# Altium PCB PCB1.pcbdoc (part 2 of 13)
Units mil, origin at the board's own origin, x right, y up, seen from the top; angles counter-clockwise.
Board outline 5895.51 x 5895.51 mil, 8 copper layers (Top Layer, L2_GND1, L3_SIG1, L4_GND2, L5_PWR, L6_SIG2, L7_GND3, Bottom Layer), stack 63.761 mil thick; 673 components, 558 nets, 2797 pads, 1861 vias.
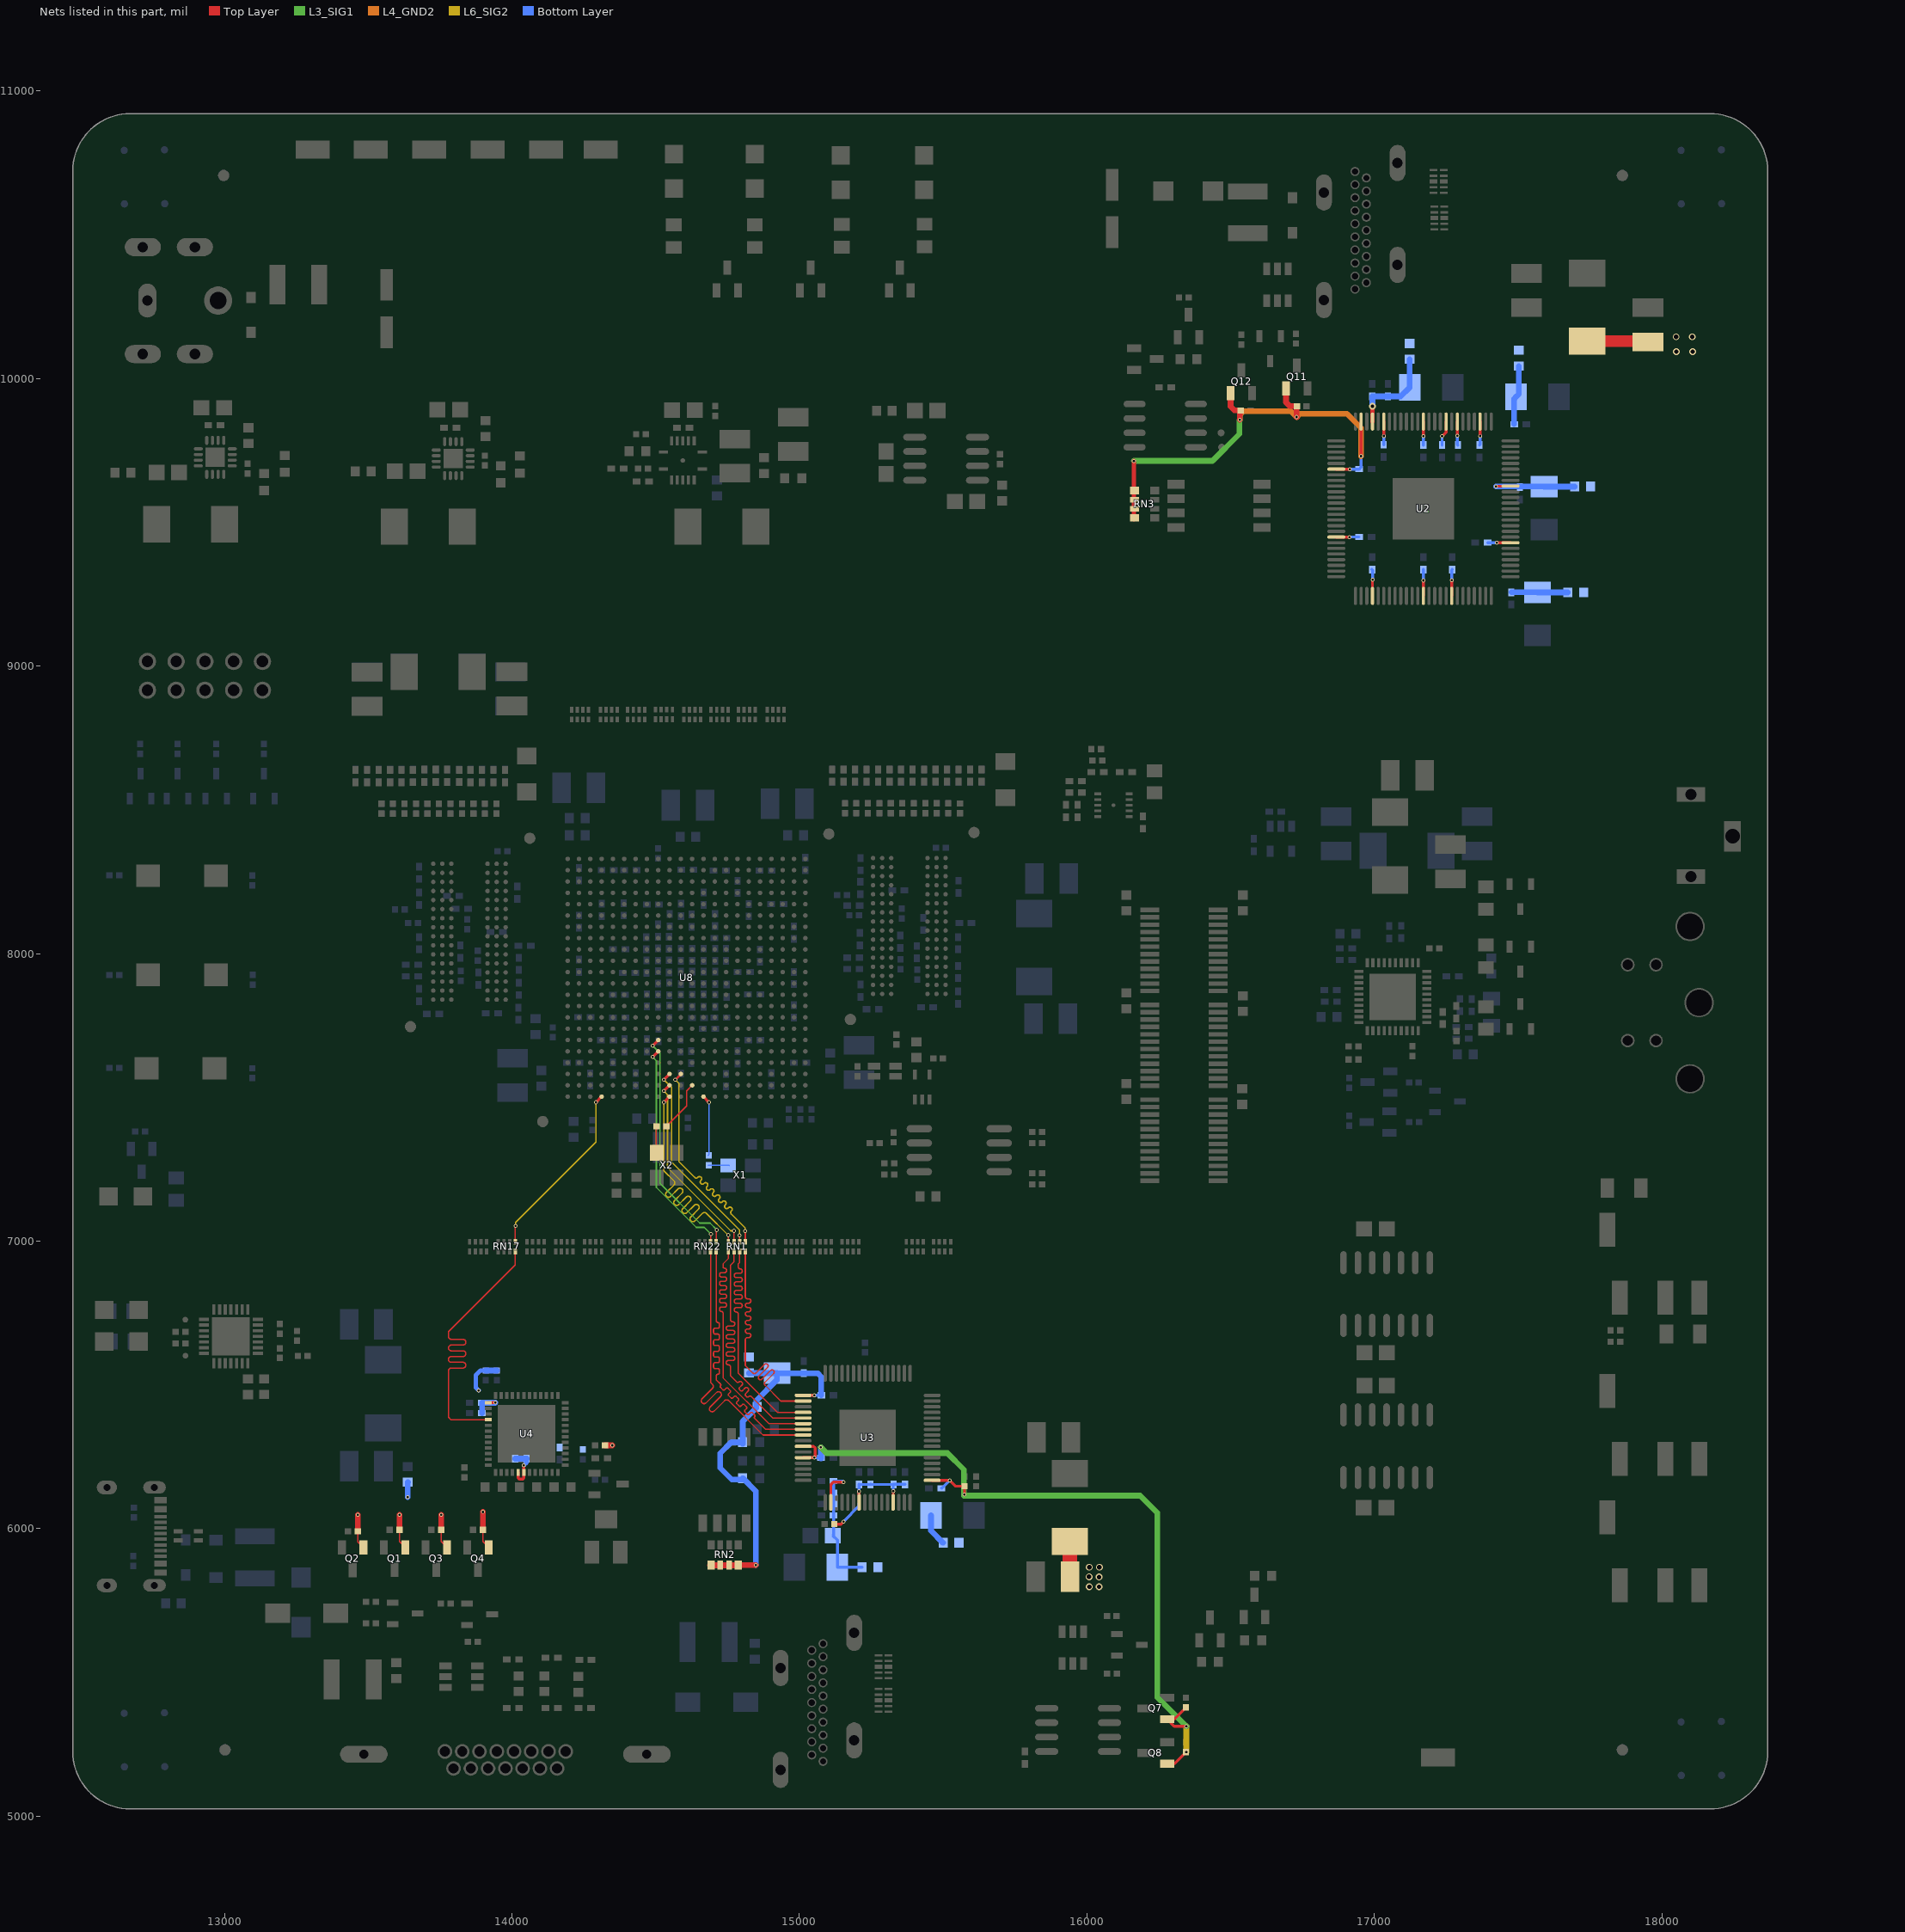
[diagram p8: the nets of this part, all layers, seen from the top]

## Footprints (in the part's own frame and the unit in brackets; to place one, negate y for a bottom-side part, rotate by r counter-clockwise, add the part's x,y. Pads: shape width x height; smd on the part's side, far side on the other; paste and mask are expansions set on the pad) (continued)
FBGA-484_L23.0-W23.0-R22-C22-P1.00-TL [mm]
  round 0.4 smd: A1(-10.5,10.5) A2(-9.5,10.5) A3(-8.5,10.5) A4(-7.5,10.5) A5(-6.5,10.5) A6(-5.5,10.5) A7(-4.5,10.5) A8(-3.5,10.5) A9(-2.5,10.5) A10(-1.5,10.5) A11(-0.5,10.5) A12(0.5,10.5) A13(1.5,10.5) A14(2.5,10.5) A15(3.5,10.5) A16(4.5,10.5) A17(5.5,10.5) A18(6.5,10.5) A19(7.5,10.5) A20(8.5,10.5) A21(9.5,10.5) A22(10.5,10.5) AA1(-10.5,-9.5) AA2(-9.5,-9.5) AA3(-8.5,-9.5) AA4(-7.5,-9.5) AA5(-6.5,-9.5) AA6(-5.5,-9.5) AA7(-4.5,-9.5) AA8(-3.5,-9.5) AA9(-2.5,-9.5) AA10(-1.5,-9.5) AA11(-0.5,-9.5) AA12(0.5,-9.5) AA13(1.5,-9.5) AA14(2.5,-9.5) AA15(3.5,-9.5) AA16(4.5,-9.5) AA17(5.5,-9.5) AA18(6.5,-9.5) AA19(7.5,-9.5) AA20(8.5,-9.5) AA21(9.5,-9.5) AA22(10.5,-9.5) AB1(-10.5,-10.5) AB2(-9.5,-10.5) AB3(-8.5,-10.5) AB4(-7.5,-10.5) AB5(-6.5,-10.5) AB6(-5.5,-10.5) AB7(-4.5,-10.5) AB8(-3.5,-10.5) AB9(-2.5,-10.5) AB10(-1.5,-10.5) AB11(-0.5,-10.5) AB12(0.5,-10.5) AB13(1.5,-10.5) AB14(2.5,-10.5) AB15(3.5,-10.5) AB16(4.5,-10.5) AB17(5.5,-10.5) AB18(6.5,-10.5) AB19(7.5,-10.5) AB20(8.5,-10.5) AB21(9.5,-10.5) AB22(10.5,-10.5) B1(-10.5,9.5) B2(-9.5,9.5) B3(-8.5,9.5) B4(-7.5,9.5) B5(-6.5,9.5) B6(-5.5,9.5) B7(-4.5,9.5) B8(-3.5,9.5) B9(-2.5,9.5) B10(-1.5,9.5) B11(-0.5,9.5) B12(0.5,9.5) B13(1.5,9.5) B14(2.5,9.5) B15(3.5,9.5) B16(4.5,9.5) B17(5.5,9.5) B18(6.5,9.5) B19(7.5,9.5) B20(8.5,9.5) B21(9.5,9.5) B22(10.5,9.5) C1(-10.5,8.5) C2(-9.5,8.5) C3(-8.5,8.5) C4(-7.5,8.5) C5(-6.5,8.5) C6(-5.5,8.5) C7(-4.5,8.5) C8(-3.5,8.5) C9(-2.5,8.5) C10(-1.5,8.5) C11(-0.5,8.5) C12(0.5,8.5) C13(1.5,8.5) C14(2.5,8.5) C15(3.5,8.5) C16(4.5,8.5) C17(5.5,8.5) C18(6.5,8.5) C19(7.5,8.5) C20(8.5,8.5) C21(9.5,8.5) C22(10.5,8.5) D1(-10.5,7.5) D2(-9.5,7.5) D3(-8.5,7.5) D4(-7.5,7.5) D5(-6.5,7.5) D6(-5.5,7.5) D7(-4.5,7.5) D8(-3.5,7.5) D9(-2.5,7.5) D10(-1.5,7.5) D11(-0.5,7.5) D12(0.5,7.5) D13(1.5,7.5) D14(2.5,7.5) D15(3.5,7.5) D16(4.5,7.5) D17(5.5,7.5) D18(6.5,7.5) D19(7.5,7.5) D20(8.5,7.5) D21(9.5,7.5) D22(10.5,7.5) E1(-10.5,6.5) E2(-9.5,6.5) E3(-8.5,6.5) E4(-7.5,6.5) E5(-6.5,6.5) E6(-5.5,6.5) E7(-4.5,6.5) E8(-3.5,6.5) E9(-2.5,6.5) E10(-1.5,6.5) E11(-0.5,6.5) E12(0.5,6.5) E13(1.5,6.5) E14(2.5,6.5) E15(3.5,6.5) E16(4.5,6.5) E17(5.5,6.5) E18(6.5,6.5) E19(7.5,6.5) E20(8.5,6.5) E21(9.5,6.5) E22(10.5,6.5) F1(-10.5,5.5) F2(-9.5,5.5) F3(-8.5,5.5) F4(-7.5,5.5) F5(-6.5,5.5) F6(-5.5,5.5) F7(-4.5,5.5) F8(-3.5,5.5) F9(-2.5,5.5) F10(-1.5,5.5) F11(-0.5,5.5) F12(0.5,5.5) F13(1.5,5.5) F14(2.5,5.5) F15(3.5,5.5) F16(4.5,5.5) F17(5.5,5.5) F18(6.5,5.5) F19(7.5,5.5) F20(8.5,5.5) F21(9.5,5.5) F22(10.5,5.5) G1(-10.5,4.5) G2(-9.5,4.5) G3(-8.5,4.5) G4(-7.5,4.5) G5(-6.5,4.5) G6(-5.5,4.5) G7(-4.5,4.5) G8(-3.5,4.5) G9(-2.5,4.5) G10(-1.5,4.5) G11(-0.5,4.5) G12(0.5,4.5) G13(1.5,4.5) G14(2.5,4.5) G15(3.5,4.5) G16(4.5,4.5) G17(5.5,4.5) G18(6.5,4.5) G19(7.5,4.5) G20(8.5,4.5) G21(9.5,4.5) G22(10.5,4.5) H1(-10.5,3.5) H2(-9.5,3.5) H3(-8.5,3.5) H4(-7.5,3.5) H5(-6.5,3.5) H6(-5.5,3.5) H7(-4.5,3.5) H8(-3.5,3.5) H9(-2.5,3.5) H10(-1.5,3.5) H11(-0.5,3.5) H12(0.5,3.5) H13(1.5,3.5) H14(2.5,3.5) H15(3.5,3.5) H16(4.5,3.5) H17(5.5,3.5) H18(6.5,3.5) H19(7.5,3.5) H20(8.5,3.5) H21(9.5,3.5) H22(10.5,3.5) J1(-10.5,2.5) J2(-9.5,2.5) J3(-8.5,2.5) J4(-7.5,2.5) J5(-6.5,2.5) J6(-5.5,2.5) J7(-4.5,2.5) J8(-3.5,2.5) J9(-2.5,2.5) J10(-1.5,2.5) J11(-0.5,2.5) J12(0.5,2.5) J13(1.5,2.5) J14(2.5,2.5) J15(3.5,2.5) J16(4.5,2.5) J17(5.5,2.5) J18(6.5,2.5) J19(7.5,2.5) J20(8.5,2.5) J21(9.5,2.5) J22(10.5,2.5) K1(-10.5,1.5) K2(-9.5,1.5) K3(-8.5,1.5) K4(-7.5,1.5) K5(-6.5,1.5) K6(-5.5,1.5) K7(-4.5,1.5) K8(-3.5,1.5) K9(-2.5,1.5) K10(-1.5,1.5) K11(-0.5,1.5) K12(0.5,1.5) K13(1.5,1.5) K14(2.5,1.5) K15(3.5,1.5) K16(4.5,1.5) K17(5.5,1.5) K18(6.5,1.5) K19(7.5,1.5) K20(8.5,1.5) K21(9.5,1.5) K22(10.5,1.5) L1(-10.5,0.5) L2(-9.5,0.5) L3(-8.5,0.5) L4(-7.5,0.5) L5(-6.5,0.5) L6(-5.5,0.5) L7(-4.5,0.5) L8(-3.5,0.5) L9(-2.5,0.5) L10(-1.5,0.5) L11(-0.5,0.5) L12(0.5,0.5) L13(1.5,0.5) L14(2.5,0.5) L15(3.5,0.5) L16(4.5,0.5) L17(5.5,0.5) L18(6.5,0.5) L19(7.5,0.5) L20(8.5,0.5) L21(9.5,0.5) L22(10.5,0.5) M1(-10.5,-0.5) M2(-9.5,-0.5) M3(-8.5,-0.5) M4(-7.5,-0.5) M5(-6.5,-0.5) M6(-5.5,-0.5) M7(-4.5,-0.5) M8(-3.5,-0.5) M9(-2.5,-0.5) M10(-1.5,-0.5) M11(-0.5,-0.5) M12(0.5,-0.5) M13(1.5,-0.5) M14(2.5,-0.5) M15(3.5,-0.5) M16(4.5,-0.5) M17(5.5,-0.5) M18(6.5,-0.5) M19(7.5,-0.5) M20(8.5,-0.5) M21(9.5,-0.5) M22(10.5,-0.5) N1(-10.5,-1.5) N2(-9.5,-1.5) N3(-8.5,-1.5) N4(-7.5,-1.5) N5(-6.5,-1.5) N6(-5.5,-1.5) N7(-4.5,-1.5) N8(-3.5,-1.5) N9(-2.5,-1.5) N10(-1.5,-1.5) N11(-0.5,-1.5) N12(0.5,-1.5) N13(1.5,-1.5) N14(2.5,-1.5) N15(3.5,-1.5) N16(4.5,-1.5) N17(5.5,-1.5) N18(6.5,-1.5) N19(7.5,-1.5) N20(8.5,-1.5) N21(9.5,-1.5) N22(10.5,-1.5) P1(-10.5,-2.5) P2(-9.5,-2.5) P3(-8.5,-2.5) P4(-7.5,-2.5) P5(-6.5,-2.5) P6(-5.5,-2.5) P7(-4.5,-2.5) P8(-3.5,-2.5) P9(-2.5,-2.5) P10(-1.5,-2.5) P11(-0.5,-2.5) P12(0.5,-2.5) P13(1.5,-2.5) P14(2.5,-2.5) P15(3.5,-2.5) P16(4.5,-2.5) P17(5.5,-2.5) P18(6.5,-2.5) P19(7.5,-2.5) P20(8.5,-2.5) P21(9.5,-2.5) P22(10.5,-2.5) R1(-10.5,-3.5) R2(-9.5,-3.5) R3(-8.5,-3.5) R4(-7.5,-3.5) R5(-6.5,-3.5) R6(-5.5,-3.5) R7(-4.5,-3.5) R8(-3.5,-3.5) R9(-2.5,-3.5) R10(-1.5,-3.5) R11(-0.5,-3.5) R12(0.5,-3.5) R13(1.5,-3.5) R14(2.5,-3.5) R15(3.5,-3.5) R16(4.5,-3.5) R17(5.5,-3.5) R18(6.5,-3.5) R19(7.5,-3.5) R20(8.5,-3.5) R21(9.5,-3.5) R22(10.5,-3.5) T1(-10.5,-4.5) T2(-9.5,-4.5) T3(-8.5,-4.5) T4(-7.5,-4.5) T5(-6.5,-4.5) T6(-5.5,-4.5) T7(-4.5,-4.5) T8(-3.5,-4.5) T9(-2.5,-4.5) T10(-1.5,-4.5) T11(-0.5,-4.5) T12(0.5,-4.5) T13(1.5,-4.5) T14(2.5,-4.5) T15(3.5,-4.5) T16(4.5,-4.5) T17(5.5,-4.5) T18(6.5,-4.5) T19(7.5,-4.5) T20(8.5,-4.5) T21(9.5,-4.5) T22(10.5,-4.5) U1(-10.5,-5.5) U2(-9.5,-5.5) U3(-8.5,-5.5) U4(-7.5,-5.5) U5(-6.5,-5.5) U6(-5.5,-5.5) U7(-4.5,-5.5) U8(-3.5,-5.5) U9(-2.5,-5.5) U10(-1.5,-5.5) U11(-0.5,-5.5) U12(0.5,-5.5) U13(1.5,-5.5) U14(2.5,-5.5) U15(3.5,-5.5) U16(4.5,-5.5) U17(5.5,-5.5) U18(6.5,-5.5) U19(7.5,-5.5) U20(8.5,-5.5) U21(9.5,-5.5) U22(10.5,-5.5) V1(-10.5,-6.5) V2(-9.5,-6.5) V3(-8.5,-6.5) V4(-7.5,-6.5) V5(-6.5,-6.5) V6(-5.5,-6.5) V7(-4.5,-6.5) V8(-3.5,-6.5) V9(-2.5,-6.5) V10(-1.5,-6.5) V11(-0.5,-6.5) V12(0.5,-6.5) V13(1.5,-6.5) V14(2.5,-6.5) V15(3.5,-6.5) V16(4.5,-6.5) V17(5.5,-6.5) V18(6.5,-6.5) V19(7.5,-6.5) V20(8.5,-6.5) V21(9.5,-6.5) V22(10.5,-6.5) W1(-10.5,-7.5) W2(-9.5,-7.5) W3(-8.5,-7.5) W4(-7.5,-7.5) W5(-6.5,-7.5) W6(-5.5,-7.5) W7(-4.5,-7.5) W8(-3.5,-7.5) W9(-2.5,-7.5) W10(-1.5,-7.5) W11(-0.5,-7.5) W12(0.5,-7.5) W13(1.5,-7.5) W14(2.5,-7.5) W15(3.5,-7.5) W16(4.5,-7.5) W17(5.5,-7.5) W18(6.5,-7.5) W19(7.5,-7.5) W20(8.5,-7.5) W21(9.5,-7.5) W22(10.5,-7.5) Y1(-10.5,-8.5) Y2(-9.5,-8.5) Y3(-8.5,-8.5) Y4(-7.5,-8.5) Y5(-6.5,-8.5) Y6(-5.5,-8.5) Y7(-4.5,-8.5) Y8(-3.5,-8.5) Y9(-2.5,-8.5) Y10(-1.5,-8.5) Y11(-0.5,-8.5) Y12(0.5,-8.5) Y13(1.5,-8.5) Y14(2.5,-8.5) Y15(3.5,-8.5) Y16(4.5,-8.5) Y17(5.5,-8.5) Y18(6.5,-8.5) Y19(7.5,-8.5) Y20(8.5,-8.5) Y21(9.5,-8.5) Y22(10.5,-8.5)
  silkscreen extent -12.06,-11.5 11.5,11.94
HDMI-SMD_HDMI-001C [mm]
  round 0.8 hole 0.55: 1(5.3,0.5) 2(4.731,-0.5) 3(4.145,0.5) 4(3.575,-0.5) 5(2.99,0.5) 6(2.419,-0.5) 7(1.835,0.5) 8(1.263,-0.5) 9(0.68,0.5) 10(0.107,-0.5) 11(-0.475,0.5) 12(-1.049,-0.5) 13(-1.63,0.5) 14(-2.205,-0.5) 15(-2.785,0.5) 16(-3.361,-0.5) 17(-3.94,0.5) 18(-4.517,-0.5) 19(-5.095,0.5)
  oval 3.2x1.4 hole 0.9 slot 2.7 at 0 deg: 20(-6.05,3.25) 20(-2.95,-3.25) 20(3.45,3.25) 20(6.05,-3.25)
  Board Outline Layer circle w0.003: c7.2,1.5 r1.016
  Board Outline Layer circle w0.003: c-6.05,-2 r1.016
  Board Outline Layer region: 7.2,2.516 7.641,2.415 7.994,2.133 8.191,1.726 8.191,1.274 7.994,0.867 7.641,0.585 7.2,0.484 7.2,0.484 6.759,0.585 6.406,0.867 6.209,1.274 6.209,1.726 6.406,2.133 6.759,2.415 7.2,2.516
  Board Outline Layer region: 7.2,2.516 7.641,2.415 7.994,2.133 8.191,1.726 8.191,1.274 7.994,0.867 7.641,0.585 7.2,0.484 7.2,0.484 6.759,0.585 6.406,0.867 6.209,1.274 6.209,1.726 6.406,2.133 6.759,2.415 7.2,2.516
  Board Outline Layer region: -6.05,-0.984 -5.609,-1.085 -5.256,-1.367 -5.059,-1.774 -5.059,-2.226 -5.256,-2.634 -5.609,-2.916 -6.05,-3.016 -6.05,-3.016 -6.491,-2.916 -6.844,-2.634 -7.04,-2.226 -7.04,-1.774 -6.844,-1.367 -6.491,-1.085 -6.05,-0.984
  Board Outline Layer region: -6.05,-0.984 -5.609,-1.085 -5.256,-1.367 -5.059,-1.774 -5.059,-2.226 -5.256,-2.634 -5.609,-2.916 -6.05,-3.016 -6.05,-3.016 -6.491,-2.916 -6.844,-2.634 -7.04,-2.226 -7.04,-1.774 -6.844,-1.367 -6.491,-1.085 -6.05,-0.984
  silkscreen extent -7.4,-3.85 15.7,3.25
HTQFP-64_L10.0-W10.0-P0.50-LS12.0-BL-EP5.0 [mm]
  oval 0.3x1.5 smd: 1(-3.75,-5.7) 2(-3.25,-5.7) 3(-2.75,-5.7) 4(-2.25,-5.7) 5(-1.75,-5.7) 6(-1.25,-5.7) 7(-0.75,-5.7) 8(-0.25,-5.7) 9(0.25,-5.7) 10(0.75,-5.7) 11(1.25,-5.7) 12(1.75,-5.7) 13(2.25,-5.7) 14(2.75,-5.7) 15(3.25,-5.7) 16(3.75,-5.7) 33(3.75,5.7) 34(3.25,5.7) 35(2.75,5.7) 36(2.25,5.7) 37(1.75,5.7) 38(1.25,5.7) 39(0.75,5.7) 40(0.25,5.7) 41(-0.25,5.7) 42(-0.75,5.7) 43(-1.25,5.7) 44(-1.75,5.7) 45(-2.25,5.7) 46(-2.75,5.7) 47(-3.25,5.7) 48(-3.75,5.7)
  oval 1.5x0.3 smd: 17(5.7,-3.75) 18(5.7,-3.25) 19(5.7,-2.75) 20(5.7,-2.25) 21(5.7,-1.75) 22(5.7,-1.25) 23(5.7,-0.75) 24(5.7,-0.25) 25(5.7,0.25) 26(5.7,0.75) 27(5.7,1.25) 28(5.7,1.75) 29(5.7,2.25) 30(5.7,2.75) 31(5.7,3.25) 32(5.7,3.75) 49(-5.7,3.75) 50(-5.7,3.25) 51(-5.7,2.75) 52(-5.7,2.25) 53(-5.7,1.75) 54(-5.7,1.25) 55(-5.7,0.75) 56(-5.7,0.25) 57(-5.7,-0.25) 58(-5.7,-0.75) 59(-5.7,-1.25) 60(-5.7,-1.75) 61(-5.7,-2.25) 62(-5.7,-2.75) 63(-5.7,-3.25) 64(-5.7,-3.75)
  rect 5x5 smd: 65(0,0)
  silkscreen extent -5.08,-6.9 5.08,5.08
HTQFP-100_L14.0-W14.0-P0.50-LS16.0-BL-EP6.2 [mm]
  oval 0.28x1.6 smd: 1(-6,-7.7) 2(-5.5,-7.7) 3(-5,-7.7) 4(-4.5,-7.7) 5(-4,-7.7) 6(-3.5,-7.7) 7(-3,-7.7) 8(-2.5,-7.7) 9(-2,-7.7) 10(-1.5,-7.7) 11(-1,-7.7) 12(-0.5,-7.7) 13(0,-7.7) 14(0.5,-7.7) 15(1,-7.7) 16(1.5,-7.7) 17(2,-7.7) 18(2.5,-7.7) 19(3,-7.7) 20(3.5,-7.7) 21(4,-7.7) 22(4.5,-7.7) 23(5,-7.7) 24(5.5,-7.7) 25(6,-7.7) 51(6,7.7) 52(5.5,7.7) 53(5,7.7) 54(4.5,7.7) 55(4,7.7) 56(3.5,7.7) 57(3,7.7) 58(2.5,7.7) 59(2,7.7) 60(1.5,7.7) 61(1,7.7) 62(0.5,7.7) 63(0,7.7) 64(-0.5,7.7) 65(-1,7.7) 66(-1.5,7.7) 67(-2,7.7) 68(-2.5,7.7) 69(-3,7.7) 70(-3.5,7.7) 71(-4,7.7) 72(-4.5,7.7) 73(-5,7.7) 74(-5.5,7.7) 75(-6,7.7)
  oval 1.6x0.28 smd: 26(7.7,-6) 27(7.7,-5.5) 28(7.7,-5) 29(7.7,-4.5) 30(7.7,-4) 31(7.7,-3.5) 32(7.7,-3) 33(7.7,-2.5) 34(7.7,-2) 35(7.7,-1.5) 36(7.7,-1) 37(7.7,-0.5) 38(7.7,0) 39(7.7,0.5) 40(7.7,1) 41(7.7,1.5) 42(7.7,2) 43(7.7,2.5) 44(7.7,3) 45(7.7,3.5) 46(7.7,4) 47(7.7,4.5) 48(7.7,5) 49(7.7,5.5) 50(7.7,6) 76(-7.7,6) 77(-7.7,5.5) 78(-7.7,5) 79(-7.7,4.5) 80(-7.7,4) 81(-7.7,3.5) 82(-7.7,3) 83(-7.7,2.5) 84(-7.7,2) 85(-7.7,1.5) 86(-7.7,1) 87(-7.7,0.5) 88(-7.7,0) 89(-7.7,-0.5) 90(-7.7,-1) 91(-7.7,-1.5) 92(-7.7,-2) 93(-7.7,-2.5) 94(-7.7,-3) 95(-7.7,-3.5) 96(-7.7,-4) 97(-7.7,-4.5) 98(-7.7,-5) 99(-7.7,-5.5) 100(-7.7,-6)
  rect 5.445x5.445 smd: 101(0,0)
  silkscreen extent -7.08,-8.9 7.08,7.08
IDC-TH_10P-P2.54_C5665 [mil]
  round 60 hole 39.37: 1(-200,-50) 2(-200,50) 3(-100,-50) 4(-100,50) 5(0,-50) 6(0,50) 7(100,-50) 8(100,50) 9(200,-50) 10(200,50)
  silkscreen extent -400,-175 400,173
IND-SMD_4P-L2.0-W1.2-TL [mm]
  rect 0.8x0.4 smd: 1(-0.901,0.399) 2(-0.899,-0.4) 3(0.9,-0.4) 4(0.901,0.4)
  silkscreen extent -0.5,-0.6 0.5,0.6
IND-SMD_L7.0-W6.6 [mm]
  rect 2.4x3.2 smd: 1(-3,0) 2(3,0)
  silkscreen extent -3.5,-3.3 3.5,3.3
KEY-SMD_2P-L6.0-W6.0-P6.00 [mm]
  rect 2.1x2 smd: 1(-3,0) 2(3,0)
  silkscreen extent -3,-3 3,3
L0603 [mm]
  rect 0.8x0.864 smd: 1(-0.7,0) 2(0.7,0)
  silkscreen extent -1.42,-0.65 1.41,0.67
L0805 [mil]
  rect 44.59x54.21 smd: 1(-38.04,0) 2(38.04,0)
  silkscreen extent -77,-40 73,40
LED1206-RD [mm]
  rect 1.635x1.6 smd: 1(-1.517,0) 2(1.517,0)
  silkscreen extent -2.99,-1.04 2.57,1.07
LED-ARRAY-SMD_4P-L1.9-W1.6-BL-CW [mm]
  rect 1.1x0.6 smd: 1(-0.95,-0.45) 2(-0.95,0.45) 3(0.95,0.45) 4(0.95,-0.45)
  silkscreen extent -1.52,-1.4 0.89,1.02
LFCSP-40_L6.0-W6.0-P0.50-BL-EP4.1 [mm]
  rect 0.28x0.8 smd: 1(-2.25,-3) 2(-1.75,-3) 3(-1.25,-3) 4(-0.75,-3) 5(-0.25,-3) 6(0.25,-3) 7(0.75,-3) 8(1.25,-3) 9(1.75,-3) 10(2.25,-3) 21(2.25,3) 22(1.75,3) 23(1.25,3) 24(0.75,3) 25(0.25,3) 26(-0.25,3) 27(-0.75,3) 28(-1.25,3) 29(-1.75,3) 30(-2.25,3)
  rect 0.8x0.28 smd: 11(3,-2.25) 12(3,-1.75) 13(3,-1.25) 14(3,-0.75) 15(3,-0.25) 16(3,0.25) 17(3,0.75) 18(3,1.25) 19(3,1.75) 20(3,2.25) 31(-3,2.25) 32(-3,1.75) 33(-3,1.25) 34(-3,0.75) 35(-3,0.25) 36(-3,-0.25) 37(-3,-0.75) 38(-3,-1.25) 39(-3,-1.75) 40(-3,-2.25)
  rect 4.1x4.1 smd: 41(0,0)
  silkscreen extent -3.2,-3.95 3.2,3.2
LFCSP-48_L7.0-W7.0-P0.50-BL-EP5.1 [mm]
  rect 0.3x0.6 smd: 1(-2.75,-3.4) 2(-2.25,-3.4) 3(-1.75,-3.4) 4(-1.25,-3.4) 5(-0.75,-3.4) 6(-0.25,-3.4) 7(0.25,-3.4) 8(0.75,-3.4) 9(1.25,-3.4) 10(1.75,-3.4) 11(2.25,-3.4) 12(2.75,-3.4) 25(2.75,3.4) 26(2.25,3.4) 27(1.75,3.4) 28(1.25,3.4) 29(0.75,3.4) 30(0.25,3.4) 31(-0.25,3.4) 32(-0.75,3.4) 33(-1.25,3.4) 34(-1.75,3.4) 35(-2.25,3.4) 36(-2.75,3.4)
  rect 0.6x0.3 smd: 13(3.4,-2.75) 14(3.4,-2.25) 15(3.4,-1.75) 16(3.4,-1.25) 17(3.4,-0.75) 18(3.4,-0.25) 19(3.4,0.25) 20(3.4,0.75) 21(3.4,1.25) 22(3.4,1.75) 23(3.4,2.25) 24(3.4,2.75) 37(-3.4,2.75) 38(-3.4,2.25) 39(-3.4,1.75) 40(-3.4,1.25) 41(-3.4,0.75) 42(-3.4,0.25) 43(-3.4,-0.25) 44(-3.4,-0.75) 45(-3.4,-1.25) 46(-3.4,-1.75) 47(-3.4,-2.25) 48(-3.4,-2.75)
  rect 5.1x5.1 smd: 49(0,0)
  silkscreen extent -3.43,-4.19 3.43,3.43
MARK [mm]
  round 1 smd: 1(0,0)
  Top Layer circle w0.003: c0,0 r1
MINI_DIN_4 [mm]
  round 1.2 hole 0.9: 1(3.35,-3.8) 2(-3.35,-3.8) 3(3.35,-6.3) 4(-3.35,-6.3)
  round 2.6 hole 2.3: 5(0,0) 6(6.731,-0.8) 7(-6.731,-0.8)
  silkscreen extent -7,-8 7,5
OSC-SMD_4P-L3.2-W2.5-BL [mm]
  rect 1.4x1.2 smd: 1(-1.1,-0.875) 2(1.1,-0.875) 3(1.1,0.875) 4(-1.1,0.875)
  silkscreen extent -2.29,-1.9 2.03,1.65
QFN-28_L5.0-W5.0-P0.50-TL-EP3.3 [mm]
  rect 0.905x0.28 smd: 1(-2.377,1.5) 2(-2.377,1) 3(-2.377,0.5) 4(-2.377,0) 5(-2.377,-0.5) 6(-2.377,-1) 7(-2.377,-1.5) 15(2.377,-1.5) 16(2.377,-1) 17(2.377,-0.5) 18(2.377,0) 19(2.377,0.5) 20(2.377,1) 21(2.377,1.5)
  rect 0.28x0.905 smd: 8(-1.5,-2.377) 9(-1,-2.377) 10(-0.5,-2.377) 11(0,-2.377) 12(0.5,-2.377) 13(1,-2.377) 14(1.5,-2.377) 22(1.5,2.377) 23(1,2.377) 24(0.5,2.377) 25(0,2.377) 26(-0.5,2.377) 27(-1,2.377) 28(-1.5,2.377)
  rect 3.35x3.35 smd: 29(0,0)
  silkscreen extent -3.2,-2.58 2.58,2.58
R0402 [mm]
  rect 0.566x0.54 smd: 1(-0.433,0) 2(0.433,0)
  silkscreen extent -0.94,-0.5 0.94,0.5
R0603 [mil]
  rect 31.75x34.02 smd: 1(-29.66,0) 2(29.66,0)
  silkscreen extent -55,-26 55,26
R0805 [mm]
  rect 1.133x1.377 smd: 1(-1,0) 2(1,0)
  silkscreen extent -1.76,-0.92 1.76,0.92
R1206 [mil]
  rect 47.54x66.97 smd: 1(-58.22,0) 2(58.22,0)
  silkscreen extent -91,-42 91,42
RCA-Y [mm]
  rect 2.7x1.5 hole 1.3 slot 2.5 at 0 deg: 1(0,0)
  rect 1.3x2.5 hole 1 slot 2.2 at 90 deg: 2(3.683,3.683) 3(-3.556,3.683)
  silkscreen extent -4.95,-11.84 5.05,5.46
RES-ADJ-SMD_3224W [mm]
  rect 1.3x2 smd: 1(-1.25,-1.45) 3(1.25,-1.45)
  rect 2x1.6 smd: 2(0,1.45)
  silkscreen extent -2.36,-3.36 2.47,1.77
RES-ARRAY-SMD_0402-8P-L2.0-W1.0-BL [mm]
  rect 0.3x0.505 smd: 1(-0.75,0.427) 2(-0.25,0.427) 3(0.25,0.427) 4(0.75,0.427) 5(0.75,-0.427) 6(0.25,-0.427) 7(-0.25,-0.427) 8(-0.75,-0.427)
  silkscreen extent -1.23,-0.91 1.23,0.91
RES-ARRAY-SMD_0603-8P-L3.2-W1.6-BL [mm]
  rect 0.65x0.8 smd: 1(-1.2,-0.9) 4(1.2,-0.9) 5(1.2,0.9) 8(-1.2,0.9)
  rect 0.5x0.8 smd: 2(-0.4,-0.9) 3(0.4,-0.9) 6(0.4,0.9) 7(-0.4,0.9)
  silkscreen extent -1.87,-1.45 1.87,1.47
SC-70-5_L2.0-W1.3-P0.65-LS2.1-BL [mm]
  rect 0.35x0.85 smd: 1(-0.65,-1.1) 2(0,-1.1) 3(0.65,-1.1) 4(0.65,1.1) 5(-0.65,1.1)
  silkscreen extent -1.12,-0.96 1,0.5
SLP2510P8_L2.5-W1.0-P0.50-BL [mm]
  rect 0.2x0.68 smd: 1(-1,-0.44) 2(-0.5,-0.44) 4(0.5,-0.44) 5(1,-0.44) 6(1,0.44) 7(0.5,0.44) 9(-0.5,0.44) 10(-1,0.44)
  rect 0.4x0.68 smd: 3(0,-0.44) 8(0,0.44)
  silkscreen extent -1.44,-0.88 1.3,0.55
SMA_L4.2-W2.6-LS5.3-RD [mm]
  rect 2.2x1.7 smd: 1(-2.565,0) 2(2.565,0)
  silkscreen extent -3.08,-1.44 2.7,1.44
SMA_L4.4-W2.6-LS5.0-RD [mm]
  rect 1.8x1.7 smd: 1(-2.192,0) 2(2.192,0)
  silkscreen extent -3.11,-1.48 2.73,1.48
SMD_SMTSO3060CTJ [mil]
  round 25.18 smd: 1(70.44,92.11) 2(69.62,-93.95) 3(-70.44,-93.25) 4(-69.65,93.95)
  Top Layer region: 7.51,99.61 13.17,99.11 21.88,97.61 29.95,95.32 35.17,93.54 41.38,91.04 46.31,88.61 52.53,85.11 57.03,81.89 61.81,78.68 66.24,74.82 70.17,71.04 73.81,67.32 78.03,62.25 82.24,56.61 85.53,51.32 88.95,45.32 91.81,38.89 94.45,31.89 96.31,26.11 98.67,15.82 99.31,8.68 99.67,4.39 133.38,4.32 132.95,12.32 132.38,16.97 131.1,25.04 129.67,32.39 127.81,38.54 125.1,46.39 121.95,54.61 116.6,65.25 112.24,72.97 105.67,81.97 98.95,89.89 92.67,96.11 86.17,101.97 80.6,106.47 73.81,111.47 66.03,116.11 58.17,120.25 50.6,123.82 41.53,127.04 31.03,130.04 23.53,131.61 15.17,132.82 7.53,133.39
  Top Layer region: 100.38,-8.02 99.87,-13.69 98.37,-22.4 96.08,-30.47 94.3,-35.69 91.8,-41.9 89.37,-46.83 85.87,-53.04 82.66,-57.54 79.44,-62.33 75.58,-66.76 71.8,-70.69 68.08,-74.33 63.01,-78.54 57.37,-82.76 52.08,-86.04 46.08,-89.47 39.66,-92.33 32.66,-94.97 26.87,-96.83 16.58,-99.19 9.44,-99.83 5.16,-100.19 5.08,-133.9 13.08,-133.47 17.73,-132.9 25.8,-131.61 33.16,-130.19 39.3,-128.33 47.16,-125.61 55.37,-122.47 66.01,-117.11 73.73,-112.76 82.73,-106.19 90.66,-99.47 96.87,-93.19 102.73,-86.69 107.23,-81.11 112.23,-74.33 116.87,-66.54 121.01,-58.69 124.58,-51.11 127.8,-42.04 130.8,-31.54 132.37,-24.04 133.58,-15.69 134.16,-8.04
  Top Layer region: -7.5,-100.75 -13.16,-100.24 -21.88,-98.74 -29.95,-96.46 -35.16,-94.67 -41.38,-92.17 -46.31,-89.74 -52.52,-86.24 -57.02,-83.03 -61.81,-79.81 -66.24,-75.96 -70.16,-72.17 -73.81,-68.46 -78.02,-63.39 -82.24,-57.74 -85.52,-52.46 -88.95,-46.46 -91.81,-40.03 -94.45,-33.03 -96.31,-27.24 -98.66,-16.96 -99.31,-9.81 -99.66,-5.53 -133.38,-5.46 -132.95,-13.46 -132.38,-18.1 -131.09,-26.17 -129.66,-33.53 -127.81,-39.67 -125.09,-47.53 -121.95,-55.74 -116.59,-66.39 -112.24,-74.1 -105.66,-83.1 -98.95,-91.03 -92.66,-97.24 -86.16,-103.1 -80.59,-107.6 -73.81,-112.6 -66.02,-117.24 -58.16,-121.39 -50.59,-124.96 -41.52,-128.17 -31.02,-131.17 -23.52,-132.74 -15.16,-133.96 -7.52,-134.53
  Top Layer region: -100.42,8.03 -99.91,13.69 -98.41,22.4 -96.12,30.47 -94.34,35.69 -91.84,41.9 -89.41,46.83 -85.91,53.05 -82.7,57.55 -79.48,62.33 -75.62,66.76 -71.84,70.69 -68.12,74.33 -63.05,78.55 -57.41,82.76 -52.12,86.05 -46.12,89.47 -39.7,92.33 -32.7,94.97 -26.91,96.83 -16.62,99.19 -9.48,99.83 -5.2,100.19 -5.12,133.9 -13.12,133.47 -17.77,132.9 -25.84,131.62 -33.2,130.19 -39.34,128.33 -47.2,125.62 -55.41,122.47 -66.05,117.12 -73.77,112.76 -82.77,106.19 -90.7,99.47 -96.91,93.19 -102.77,86.69 -107.27,81.12 -112.27,74.33 -116.91,66.55 -121.05,58.69 -124.62,51.12 -127.84,42.05 -130.84,31.55 -132.41,24.05 -133.62,15.69 -134.2,8.05
  Board Outline Layer circle w0.1: c-0.15,-0.01 r86.61
  Board Outline Layer region: -86.77,-0.01 -78.19,-37.59 -54.16,-67.73 -19.43,-84.45 19.12,-84.45 53.85,-67.73 77.88,-37.59 86.46,-0.01 86.46,-0.01 77.88,37.57 53.85,67.71 19.12,84.43 -19.43,84.43 -54.16,67.71 -78.19,37.57 -86.77,-0.01
  Board Outline Layer region: -86.77,-0.01 -78.19,-37.59 -54.16,-67.73 -19.43,-84.45 19.12,-84.45 53.85,-67.73 77.88,-37.59 86.46,-0.01 86.46,-0.01 77.88,37.57 53.85,67.71 19.12,84.43 -19.43,84.43 -54.16,67.71 -78.19,37.57 -86.77,-0.01
  silkscreen extent -142,-141 141,141
SOD-123F_L2.6-W1.6-LS3.5-RD [mm]
  rect 1x0.84 smd: 1(-1.55,0) 2(1.55,0)
  silkscreen extent -1.38,-0.88 1.38,0.88
SOD-123FL_L2.8-W1.8-LS3.7-RD-1 [mm]
  rect 0.93x1.2 smd: 1(-1.65,0) 2(1.65,0)
  silkscreen extent -1.6,-0.95 1.38,0.95
SOIC-8_L4.9-W3.9-P1.27-LS6.0-BL [mm]
  oval 0.588x2.045 smd: 1(-1.905,-2.772) 2(-0.635,-2.772) 3(0.635,-2.772) 4(1.905,-2.772) 5(1.905,2.772) 6(0.635,2.772) 7(-0.635,2.772) 8(-1.905,2.772)
  silkscreen extent -2.8,-2.92 2.53,1.52
SOIC-8_L5.0-W4.0-P1.27-LS6.0-BL [mil]
  oval 22.38x76.78 smd: 1(-75,-106.5) 2(-25,-106.5) 3(25,-106.5) 4(75,-106.5) 5(75,106.5) 6(25,106.5) 7(-25,106.5) 8(-75,106.5)
  silkscreen extent -106,-111 98,75
SOIC-8_L5.3-W5.3-P1.27-LS8.0-BL [mm]
  oval 0.63x2.25 smd: 1(-1.905,-3.53) 2(-0.635,-3.53) 3(0.635,-3.53) 4(1.905,-3.53) 5(1.905,3.53) 6(0.635,3.53) 7(-0.635,3.53) 8(-1.905,3.53)
  silkscreen extent -2.82,-3.68 2.64,2.18
SOIC-14_L8.7-W3.9-P1.27-LS6.0-BL [mil]
  oval 22.6x80.24 smd: 1(-150,-109.02) 2(-100,-109.02) 3(-50,-109.02) 4(0,-109.02) 5(50,-109.02) 6(100,-109.02) 7(150,-109.02) 8(150,109.02) 9(100,109.02) 10(50,109.02) 11(0,109.02) 12(-50,109.02) 13(-100,109.02) 14(-150,109.02)
  silkscreen extent -185,-115 173,60
SOT-23-3_L2.9-W1.3-P1.90-LS2.4-BR [mm]
  rect 1.25x0.7 smd: 1(1,-0.95) 2(1,0.95) 3(-1,0)
  silkscreen extent -0.73,-1.53 0.73,1.53
SOT-23-3_L2.9-W1.6-P1.90-LS2.8-BR [mm]
  rect 1.07x0.6 smd: 1(1.235,-0.95) 2(1.235,0.95) 3(-1.235,0)
  silkscreen extent -0.88,-1.54 0.88,1.54
SOT-23-3_L3.0-W1.7-P0.95-LS2.9-BR [mil]
  rect 40.85x20.95 smd: 1(43.36,-37.4) 2(43.36,37.4) 3(-43.36,0)
  silkscreen extent -34,-60 34,60
SOT-23-5_L2.9-W1.6-P0.95-LS2.8-BR [mm]
  rect 1x0.6 smd: 1(1.1,-0.95) 2(1.1,0) 3(1.1,0.95) 4(-1.1,0.95) 5(-1.1,-0.95)
  silkscreen extent -0.89,-1.52 0.7,1.4
SOT-23-6_L2.9-W1.6-P0.95-LS2.7-BL [mm]
  rect 0.6x1.1 smd: 1(-0.95,-1.4) 2(0,-1.4) 3(0.95,-1.4) 4(0.95,1.4) 5(0,1.4) 6(-0.95,1.4)
  silkscreen extent -1.82,-1.45 1.54,0.89
SW-SMD_8P-L6.7-W5.4-P1.27-LS8.4 [mil]
  rect 30x60 smd: 1(-75,-150) 2(-25,-150) 3(25,-150) 4(75,-150) 5(75,150) 6(25,150) 7(-25,150) 8(-75,150)
  silkscreen extent -132,-106 132,106
Test-Point-0.5mm [mm]
  round 0.5 smd: 1(0,0)
TEST-RING [mm]
  rect 3x1.6 smd: 1(0,0)
  silkscreen extent -1.78,-1.02 1.78,1.02
TQFN-16_L3.0-W3.0-P0.50-TL-EP1.7 [mm]
  oval 0.8x0.28 smd: 1(-1.5,0.75) 2(-1.5,0.25) 3(-1.5,-0.25) 4(-1.5,-0.75) 9(1.5,-0.75) 10(1.5,-0.25) 11(1.5,0.25) 12(1.5,0.75)
  oval 0.28x0.8 smd: 5(-0.75,-1.5) 6(-0.25,-1.5) 7(0.25,-1.5) 8(0.75,-1.5) 13(0.75,1.5) 14(0.25,1.5) 15(-0.25,1.5) 16(-0.75,1.5)
  rect 1.7x1.7 smd: 17(0,0)
  silkscreen extent -2.38,-1.72 1.72,1.73
TSSOP-24_L7.8-W4.4-P0.65-LS6.4-BL [mm]
  rect 0.4x1.65 smd: 1(-3.575,-3.023) 2(-2.925,-3.023) 3(-2.275,-3.023) 4(-1.625,-3.023) 5(-0.975,-3.023) 6(-0.325,-3.023) 7(0.325,-3.023) 8(0.975,-3.023) 9(1.625,-3.023) 10(2.275,-3.023) 11(2.925,-3.023) 12(3.575,-3.023) 13(3.575,3.023) 14(2.925,3.023) 15(2.275,3.023) 16(1.625,3.023) 17(0.975,3.023) 18(0.325,3.023) 19(-0.325,3.023) 20(-0.975,3.023) 21(-1.625,3.023) 22(-2.275,3.023) 23(-2.925,3.023) 24(-3.575,3.023)
  silkscreen extent -4.24,-3.15 3.94,2.01
USB-C-SMD_TYPE-C-6PIN-2MD-073 [mm]
  rect 0.55x1.1 smd: 1(-3.2,2.375) 2(-2.4,2.375) 11(2.4,2.375) 12(3.2,2.375)
  rect 0.3x1.1 smd: 3(-1.75,2.375) 4(-1.25,2.375) 5(-0.75,2.375) 6(-0.25,2.375) 7(0.25,2.375) 8(0.75,2.375) 9(1.25,2.375) 10(1.75,2.375)
  oval 1.2x1.8 hole 0.6 slot 1.2 at 90 deg: 13(-4.325,-2.375) 14(4.325,-2.375)
  oval 1.1x2 hole 0.6 slot 1.5 at 90 deg: 13(-4.325,1.825) 14(4.325,1.825)
  Board Outline Layer circle w0.003: c-2.89,1.305 r0.35
  Board Outline Layer circle w0.003: c2.89,1.305 r0.35
  Board Outline Layer region: -2.89,1.655 -2.738,1.62 -2.616,1.523 -2.549,1.383 -2.549,1.227 -2.616,1.087 -2.738,0.99 -2.89,0.955 -2.89,0.955 -3.042,0.99 -3.164,1.087 -3.231,1.227 -3.231,1.383 -3.164,1.523 -3.042,1.62 -2.89,1.655
  Board Outline Layer region: -2.89,1.655 -2.738,1.62 -2.616,1.523 -2.549,1.383 -2.549,1.227 -2.616,1.087 -2.738,0.99 -2.89,0.955 -2.89,0.955 -3.042,0.99 -3.164,1.087 -3.231,1.227 -3.231,1.383 -3.164,1.523 -3.042,1.62 -2.89,1.655
  Board Outline Layer region: 2.89,1.655 3.042,1.62 3.164,1.523 3.231,1.383 3.231,1.227 3.164,1.087 3.042,0.99 2.89,0.955 2.89,0.955 2.738,0.99 2.616,1.087 2.549,1.227 2.549,1.383 2.616,1.523 2.738,1.62 2.89,1.655
  Board Outline Layer region: 2.89,1.655 3.042,1.62 3.164,1.523 3.231,1.383 3.231,1.227 3.164,1.087 3.042,0.99 2.89,0.955 2.89,0.955 2.738,0.99 2.616,1.087 2.549,1.227 2.549,1.383 2.616,1.523 2.738,1.62 2.89,1.655
  silkscreen extent -4.5,-4.97 4.57,0.6
VQFN-14_L3.5-W3.5-P0.50-TL-EP_TPS54622RHLT [mm]
  rect 0.28x0.8 smd: 1(-0.75,1.725) 7(-0.75,-1.725) 8(0.75,-1.725) 14(0.75,1.725)
  rect 0.8x0.28 smd: 2(-1.725,1) 3(-1.725,0.5) 4(-1.725,0) 5(-1.725,-0.5) 6(-1.725,-1) 9(1.725,-1) 10(1.725,-0.5) 11(1.725,0) 12(1.725,0.5) 13(1.725,1)
  round 0.406 smd: 15(0,0)
  Top Layer region: -1.016,1.016 -0.4,1.016 -0.4,2.16 -0.16,2.16 -0.16,1.44 0.16,1.44 0.16,2.16 0.4,2.16 0.4,1.016 1.016,1.016 1.016,-1.016 0.4,-1.016 0.4,-2.16 0.16,-2.16 0.16,-1.44 -0.16,-1.44 -0.16,-2.16 -0.4,-2.16 -0.4,-1.016 -1.016,-1.016
  silkscreen extent -1.9,-1.9 1.9,2.54
WSON-10_L3.0-W3.0-P0.50-BL-EP [mm]
  rect 0.25x0.6 smd: 1(-1.001,-1.4) 2(-0.5,-1.4) 3(0,-1.4) 4(0.5,-1.4) 5(1.001,-1.4) 6(1.001,1.4) 7(0.5,1.4) 8(0,1.4) 9(-0.5,1.4) 10(-1.001,1.4)
  round 0.33 smd: 11(0,0)
  Top Layer region: -1.7,-0.125 -1.2,-0.125 -1.2,0.125 -1.7,0.125 -1.7,0.375 -1.2,0.375 -1.2,0.825 1.2,0.825 1.2,0.375 1.7,0.375 1.7,0.125 1.2,0.125 1.2,-0.125 1.7,-0.125 1.7,-0.375 1.2,-0.375 1.2,-0.825 -1.2,-0.825 -1.2,-0.375 -1.7,-0.375
  silkscreen extent -2.02,-1.52 1.52,1.52

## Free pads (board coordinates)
  round 24 smd: TP1(16466.71,9811) TP2(16468.53,9761)

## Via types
v1: diameter 23.62, hole 15.75, Top Layer to Bottom Layer, 621 vias
v2: diameter 13.8, hole 7.9, Top Layer to Bottom Layer, 567 vias
v3: diameter 13.78, hole 7.87, Top Layer to Bottom Layer, 529 vias
v4: diameter 13.78, hole 7.9, Top Layer to Bottom Layer, 114 vias
v5: diameter 15.75, hole 7.87, Top Layer to Bottom Layer, 16 vias
v6: diameter 24, hole 12, Top Layer to Bottom Layer, 10 vias
v7: diameter 11.81, hole 7.87, Top Layer to Bottom Layer, 4 vias

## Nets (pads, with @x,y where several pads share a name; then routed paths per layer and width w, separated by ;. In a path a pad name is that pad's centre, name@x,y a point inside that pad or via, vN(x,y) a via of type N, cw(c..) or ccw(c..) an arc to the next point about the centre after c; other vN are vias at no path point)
27M_CLK: R152.1 X1.3 | length 72.8
  Bottom Layer w4.7: R152.1@14683.15,7263.92 14754.99,7263.92 X1.3@14755.64,7263.27
27M_CLK_FPGA: R152.2 U8.AB13 | length 213.7
  Top Layer w10: U8.AB13@14666.41,7502.6 v2(14686.09,7482.92)
  Bottom Layer w4.7: R152.2@14682.61,7298.46 14686.09,7301.95 v2(14686.09,7482.92)
50M_CLK: R153.1 X2.3 | length 94.7
  Top Layer w4.7: X2.3@14501.45,7305.78 R153.1@14501.45,7400.44
50M_CLK_FPGA: R153.2 U8.AA12 | length 178.1
  Top Layer w4.7: R153.2@14538.83,7401.41 14607.51,7470.1 14607.51,7522.52 14627.55,7542.56 U8.AA12@14627.55,7542.75
401_AVDD: C173.1 C176.2 C181.1 C188.2 C189.2 C190.2 L8.2 U2.82 U2.84 U2.88 U2.95 | length 541.8
  Top Layer w10: v3(17032.56,9800) U2.95@17032.56,9850.15 ; v3(17170.36,9799) U2.88@17170.36,9850.15 ; v3(17235.36,9799) 17249.1,9812.74 U2.84@17249.1,9850.15 ; v3(17288.36,9801) 17288.47,9801.11 U2.82@17288.47,9850.15
  Bottom Layer w10: C190.2@17032.36,9769.46 17032.36,9800 v3(17032.56,9800) ; C189.2@17170.36,9768.46 v3(17170.36,9799) ; C176.2@17235.36,9768.46 v3(17235.36,9799) ; v3(17288.36,9801) 17288.36,9770.46 C188.2@17290.36,9768.46
  Bottom Layer w20: C173.1@17485.9,9841 17485.9,9929.29 C181.1@17492.61,9936 17502.36,9945.75 L8.2@17502.36,10043.44
401_DVDD: C157.1 C158.1 C166.2 C178.1 L5.2 Q11.1 Q12.1 R108.2 R109.2 RN3.1 RN3.2 RN3.3 RN3.4 U2.6 U2.38 U2.67 U2.99 | length 2149.6
  Top Layer w10: U2.6@16867.21,9684.79 v3(16914.36,9684.79) ; v3(16953.82,9730) U2.99@16953.82,9850.15 ; U2.38@17170.36,9243.85 v3(17170.36,9298) ; v3(17422.49,9624.88) 17422.71,9625.1 U2.67@17469.2,9625.1
  Top Layer w15: v3(16163.34,9713.18) 16163.67,9712.85 RN3.4@16163.67,9510.28
  Top Layer w20: Q12.1@16499.79,9949.25 16499.79,9902.57 16513.36,9889 R109.2@16534.77,9889 ; v3(16531.88,9856.14) 16531.88,9886.1 R109.2@16534.77,9889 ; R109.2@16535.15,9888.62 R109.2@16534.77,9889 ; Q11.1@16692.58,9965.94 16692.58,9916.78 16705.73,9903.62 R108.2@16729.07,9903.62 ; R108.2@16729.07,9903.98 R108.2@16729.07,9903.62 ; v3(16729.74,9865.79) 16729.07,9866.46 R108.2@16729.07,9903.62 ; R108.2@16730.15,9903.62 R108.2@16729.07,9903.62
  L3_SIG1 w20: v3(16163.34,9713.18) 16436.54,9713.18 16530.36,9807 16530.36,9854.62 v3(16531.88,9856.14)
  L4_GND2 w20: v3(16531.88,9856.14) 16531.88,9873.48 16544.4,9886 16709.53,9886 v3(16729.74,9865.79) 16740.94,9877 16904.36,9877 16953.36,9828 16953.36,9730.46 v3(16953.82,9730)
  Bottom Layer w10: v3(16914.36,9684.79) 16914.36,9684 16945.9,9684 C166.2@16946.9,9685 16953.82,9691.92 v3(16953.82,9730) ; v3(17170.36,9298) C157.1@17170.36,9335.54 ; C158.1@17504.62,9625.1 C158.1@17505.06,9624.66
  Bottom Layer w20: v3(17422.49,9624.88) 17422.71,9624.66 17505.06,9624.66 C178.1@17590.74,9624.66 ; C178.1@17590.36,9623.75 17696.55,9623.75 L5.2@17696.8,9624
401_OVDD: C159.1 C167.2 C169.2 C179.1 C185.2 C186.2 C187.2 L6.2 U2.18 U2.29 U2.43 U2.57 U2.78 | length 624.8
  Top Layer w10: U2.18@16867.21,9448.57 v3(16913.36,9448.57) ; U2.29@16993.19,9243.85 16993.19,9299.83 v3(16993.36,9300) ; U2.43@17268.78,9243.85 v3(17268.78,9299) ; U2.78@17367.21,9850.15 17367.21,9800.15 v3(17367.36,9800) ; v3(17425.36,9429) 17425.47,9428.89 U2.57@17473.51,9428.89
  Bottom Layer w10: v3(16913.36,9448.57) 16913.36,9449 C167.2@16946.9,9449 ; C185.2@16990.36,9335.54 16993.36,9332.54 v3(16993.36,9300) ; v3(17268.78,9299) 17268.78,9333.96 C186.2@17270.36,9335.54 ; C169.2@17365.36,9768.46 17367.36,9770.46 v3(17367.36,9800) ; C187.2@17393.82,9429 v3(17425.36,9429)
  Bottom Layer w20: C159.1@17476.36,9256.46 17566.65,9256.46 C179.1@17567.11,9256 ; C179.1@17567.36,9255.75 C179.1@17567.11,9256 ; L6.2@17672.8,9256 C179.1@17567.11,9256
401_PVDD: C162.1 C171.2 C180.1 L7.2 U2.97 | length 328.6
  Top Layer w15: U2.97@16993.19,9850.15 v6(16993.19,9904)
  Bottom Layer w20: v6(16993.19,9904) 16993.19,9936.71 C171.2@16992.36,9937.54 C162.1@17047.36,9937.54 17091.15,9937.54 C180.1@17122.61,9969 17122.36,9969.25 L7.2@17122.36,10066.44
401_PWR: C214.2 L5.1 L6.1 L7.1 L8.1 L31.2 | length 212.4
  Top Layer w40: L31.2@17739.86,10129.39 17949.23,10129.39 C214.2@17951.36,10127.26
  other v1: 18050.39,10093.02 18107.17,10093.02 18049.39,10144.83 18105.68,10144.83
410_CTL1: RN22.6 U3.8 | length 1102.1
  Top Layer w4.7: RN22.6@14692.2,6964.17 14691.36,6963.33 14691.36,6508 14697.44,6501.91 cw(c14690.37,6494.84) 14697.44,6487.77 14661.59,6451.91 ccw(c14668.66,6444.84) 14675.73,6437.77 14711.59,6473.63 cw(c14718.66,6466.56) 14725.73,6459.49 14689.87,6423.63 ccw(c14696.94,6416.56) 14704.01,6409.49 14739.87,6445.34 cw(c14746.94,6438.27) 14754.01,6445.34 14873.52,6325.84 U3.8@15012.95,6325.84
410_CTL1_FPGA: RN22.3 U8.V9 | length 771.4
  Top Layer w4.7: RN22.3@14691.2,6997.83 14691.2,7023.84 v3(14692.36,7025)
  Top Layer w10: v2(14489.26,7640.42) U8.V9@14508.93,7660.1
  L3_SIG1 w5: v2(14489.26,7640.42) 14502.36,7627.32 14502.36,7187 14641.36,7048 14669.36,7048 v3(14692.36,7025)
410_CTL2: RN22.5 U3.7 | length 1054.2
  Top Layer w4.7: RN22.5@14711.89,6964.17 14711.36,6963.64 14711.36,6722.11 ccw(c14716.36,6722.11) 14716.36,6717.11 cw(c14716.36,6712.11) 14721.36,6712.11 14721.36,6702.11 cw(c14716.36,6702.11) 14716.36,6697.11 14706.36,6697.11 ccw(c14706.36,6692.11) 14701.36,6692.11 14701.36,6682.11 ccw(c14706.36,6682.11) 14706.36,6677.11 14716.36,6677.11 cw(c14716.36,6672.11) 14721.36,6672.11 14721.36,6662.11 cw(c14716.36,6662.11) 14716.36,6657.11 14706.36,6657.11 ccw(c14706.36,6652.11) 14701.36,6652.11 14701.36,6642.11 ccw(c14706.36,6642.11) 14706.36,6637.11 14716.36,6637.11 cw(c14716.36,6632.11) 14721.36,6632.11 14721.36,6622.11 cw(c14716.36,6622.11) 14716.36,6617.11 14706.36,6617.11 ccw(c14706.36,6612.11) 14701.36,6612.11 14701.36,6602.11 ccw(c14706.36,6602.11) 14706.36,6597.11 14716.36,6597.11 cw(c14716.36,6592.11) 14721.36,6592.11 14721.36,6582.11 cw(c14716.36,6582.11) 14716.36,6577.11 14706.36,6577.11 ccw(c14706.36,6572.11) 14701.36,6572.11 14701.36,6562.11 ccw(c14706.36,6562.11) 14706.36,6557.11 14716.36,6557.11 cw(c14716.36,6552.11) 14721.36,6552.11 14721.36,6542.11 cw(c14716.36,6542.11) 14716.36,6537.11 ccw(c14716.36,6532.11) 14711.36,6532.11 14711.36,6517 14725.59,6502.77 cw(c14722.76,6499.94) 14725.59,6497.11 ccw(c14728.42,6494.28) 14725.59,6491.45 14734.08,6482.97 ccw(c14736.9,6485.8) 14739.73,6482.97 14745.39,6488.62 cw(c14748.22,6485.8) 14751.05,6488.62 14759.53,6480.14 cw(c14756.7,6477.31) 14759.53,6474.48 14753.88,6468.83 ; 14753.87,6463.17 cw(c14756.7,6466) 14753.87,6468.83 ; 14753.88,6463.17 14762.36,6454.68 ccw(c14765.19,6457.51) 14768.02,6454.68 14773.67,6460.34 cw(c14776.5,6457.51) 14779.33,6460.34 14787.82,6451.85 cw(c14784.99,6449.03) 14787.82,6446.2 14782.16,6440.54 ccw(c14784.99,6437.71) 14782.16,6434.88 14790.64,6426.4 ccw(c14793.47,6429.23) 14796.3,6426.4 14801.96,6432.06 cw(c14804.79,6429.23) 14807.62,6432.06 14816.1,6423.57 cw(c14813.27,6420.74) 14816.1,6417.91 14810.44,6412.26 ccw(c14813.27,6409.43) 14810.44,6406.6 14818.93,6398.11 ccw(c14821.76,6400.94) 14824.59,6398.11 14830.24,6403.77 cw(c14833.07,6400.94) 14835.9,6403.77 14844.38,6395.29 cw(c14841.56,6392.46) 14844.38,6389.63 ccw(c14847.21,6386.8) 14844.38,6383.97 14882.83,6345.53 U3.7@15012.95,6345.53
410_CTL2_FPGA: RN22.4 U8.U9 | length 823.9
  Top Layer w4.7: RN22.4@14710.89,6997.83 14710.89,7037.53 v3(14712.36,7039)
  Top Layer w10: v2(14489.26,7679.79) U8.U9@14508.93,7699.47
  L3_SIG1 w5: v2(14489.26,7679.79) 14515.36,7653.69 14515.36,7201 14653.36,7063 14689.36,7063 14712.36,7040 v3(14712.36,7039)
410_CTL3: RN1.8 U3.6 | length 974.9
  Top Layer w4.7: RN1.8@14752.83,6964.17 14752.36,6963.7 14752.36,6939 14734.36,6921 14734.36,6911.74 ccw(c14740.36,6911.74) 14740.36,6905.74 cw(c14740.36,6899.74) 14746.36,6899.74 14746.36,6896.74 cw(c14740.36,6896.74) 14740.36,6890.74 14728.36,6890.74 ccw(c14728.36,6884.74) 14722.36,6884.74 14722.36,6881.74 ccw(c14728.36,6881.74) 14728.36,6875.74 14740.36,6875.74 cw(c14740.36,6869.74) 14746.36,6869.74 14746.36,6866.74 cw(c14740.36,6866.74) 14740.36,6860.74 14728.36,6860.74 ccw(c14728.36,6854.74) 14722.36,6854.74 14722.36,6851.74 ccw(c14728.36,6851.74) 14728.36,6845.74 14740.36,6845.74 cw(c14740.36,6839.74) 14746.36,6839.74 14746.36,6836.74 cw(c14740.36,6836.74) 14740.36,6830.74 14728.36,6830.74 ccw(c14728.36,6824.74) 14722.36,6824.74 14722.36,6821.74 ccw(c14728.36,6821.74) 14728.36,6815.74 14740.36,6815.74 cw(c14740.36,6809.74) 14746.36,6809.74 14746.36,6806.74 cw(c14740.36,6806.74) 14740.36,6800.74 14728.36,6800.74 ccw(c14728.36,6794.74) 14722.36,6794.74 14722.36,6791.74 ccw(c14728.36,6791.74) 14728.36,6785.74 14740.36,6785.74 cw(c14740.36,6779.74) 14746.36,6779.74 14746.36,6776.74 cw(c14740.36,6776.74) 14740.36,6770.74 14728.36,6770.74 ccw(c14728.36,6764.74) 14722.36,6764.74 14722.36,6761.74 ccw(c14728.36,6761.74) 14728.36,6755.74 cw(c14728.36,6749.74) 14734.36,6749.74 14734.36,6525 14894.15,6365.21 U3.6@15012.95,6365.21
410_CTL3_FPGA: RN1.1 U8.AB10 | length 989.9
  Top Layer w4.7: v3(14752.36,7021) 14752.36,6998.3 RN1.1@14752.83,6997.83
  Top Layer w10: v2(14528.63,7482.92) U8.AB10@14548.3,7502.6
  L6_SIG2 w5: v2(14528.63,7482.92) 14528.63,7244.73 14563.63,7209.73 cw(c14556.56,7202.65) 14563.63,7195.58 14537.76,7169.71 ccw(c14544.83,7162.64) 14551.9,7155.57 14577.77,7181.44 cw(c14584.84,7174.37) 14591.92,7167.3 14566.04,7141.42 ccw(c14573.11,7134.35) 14580.18,7127.28 14606.06,7153.16 cw(c14613.13,7146.09) 14620.2,7139.02 14594.32,7113.14 ccw(c14601.4,7106.07) 14608.47,7099 14634.34,7124.87 cw(c14641.41,7117.8) 14648.48,7110.73 14622.61,7084.86 ccw(c14629.68,7077.78) 14636.75,7070.71 14662.63,7096.59 cw(c14669.7,7089.52) 14676.77,7096.59 v3(14752.36,7021)
410_DE: RN1.5 U3.2 | length 982.9
  Top Layer w4.7: RN1.5@14811.89,6964.17 14811.89,6807.12 ccw(c14819.39,6807.12) 14819.39,6799.62 14823.86,6799.62 cw(c14823.86,6792.12) 14823.86,6784.62 14819.39,6784.62 ccw(c14819.39,6777.12) 14819.39,6769.62 14823.86,6769.62 cw(c14823.86,6762.12) 14823.86,6754.62 14819.39,6754.62 ccw(c14819.39,6747.12) 14819.39,6739.62 14823.86,6739.62 cw(c14823.86,6732.12) 14823.86,6724.62 14819.39,6724.62 ccw(c14819.39,6717.12) 14819.39,6709.62 14823.86,6709.62 cw(c14823.86,6702.12) 14823.86,6694.62 14819.39,6694.62 ccw(c14819.39,6687.12) 14819.39,6679.62 14823.86,6679.62 cw(c14823.86,6672.12) 14823.86,6664.62 14819.39,6664.62 ccw(c14819.39,6657.12) 14811.89,6657.12 14811.89,6567.47 14837.96,6541.4 ccw(c14843.26,6546.7) 14848.57,6541.4 14878.51,6571.34 cw(c14883.81,6566.04) 14889.12,6560.74 14859.17,6530.79 ccw(c14864.48,6525.49) 14869.78,6520.18 14899.72,6550.13 cw(c14905.03,6544.83) 14910.33,6539.52 14880.39,6509.58 ccw(c14885.69,6504.27) 14880.39,6498.97 14935.41,6443.95 U3.2@15012.95,6443.95
410_DE_FPGA: RN1.4 U8.Y11 | length 808.8
  Top Layer w4.7: v3(14811.36,7035) 14811.89,7034.47 RN1.4@14811.89,6997.83
  Top Layer w7.9: v3(14568.36,7561) 14587.66,7580.3 U8.Y11@14587.66,7581.35
  L6_SIG2 w5: v3(14568.36,7561) 14580.84,7548.52 14580.84,7276.69 14636,7221.53 ccw(c14641.3,7226.83) 14646.61,7221.53 14647.41,7222.34 cw(c14652.72,7217.03) 14658.02,7211.73 14657.21,7210.92 ccw(c14662.52,7205.62) 14667.82,7200.32 14668.63,7201.12 cw(c14673.93,7195.82) 14679.23,7190.52 14678.43,7189.71 ccw(c14683.73,7184.41) 14689.03,7179.1 14689.84,7179.91 cw(c14695.14,7174.61) 14700.45,7169.3 14699.64,7168.5 ccw(c14704.94,7163.19) 14710.25,7157.89 14711.05,7158.7 cw(c14716.36,7153.39) 14721.66,7148.09 14720.85,7147.28 ccw(c14726.16,7141.98) 14731.46,7136.68 14732.27,7137.48 cw(c14737.57,7132.18) 14742.87,7126.88 14742.07,7126.07 ccw(c14747.37,7120.77) 14752.67,7115.46 14753.48,7116.27 cw(c14758.78,7110.97) 14764.09,7105.66 14763.28,7104.86 ccw(c14768.58,7099.55) 14763.28,7094.25 14811.36,7046.17 v3(14811.36,7035)
410_DVDD: C129.1 C141.2 C143.2 C182.1 C191.2 L2.2 Q7.1 Q8.1 R102.2 R104.2 R105.2 RN2.1 RN2.2 RN2.3 RN2.4 U3.1 U3.10 U3.12 U3.33 U21.1 U101.2 U121.2 | length 4203.1
  Top Layer w10: U3.12@15012.95,6247.1 v3(15051.36,6247.1) 15054.36,6250.1 15054.36,6281 15048.89,6286.47 U3.10@15012.95,6286.47 ; U3.1@15012.95,6463.64 v3(15052.36,6463.64) ; U3.33@15461.77,6168.36 15522,6168.36 v3(15522.36,6168) 15542.4,6147.96 R102.2@15574.36,6147.96 15574.36,6118.69 v3(15574.07,6118.4) ; Q8.1@16278.68,5183.01 16303.95,5183.01 R105.2@16344.31,5223.37 ; R104.2@16344.31,5378.37 16303.95,5338.01 Q7.1@16278.68,5338.01 16303.72,5312.97 v3(16345.8,5312.97)
  Top Layer w20: RN2.1@14689.24,5872.58 14787.29,5872.58 RN2.4@14788.5,5871.36 ; RN2.4@14787.6,5873.56 14788.03,5874 v3(14848.36,5874)
  L3_SIG1 w20: v3(15074.77,6282.77) 15094.77,6262.77 15514.89,6262.77 15572.23,6205.43 15572.23,6115.15 16185.16,6115.15 16244.83,6055.48 16244.83,5413.94 v3(16345.8,5312.97)
  L6_SIG2 w20: v3(16345.8,5222.99) v3(16345.8,5312.97)
  Bottom Layer w10: v3@15051.36,6247 C141.2@15074.77,6247 ; v3(15052.36,6463.64) 15052.36,6464 C143.2@15075.9,6464 ; C191.2@15493.82,6141 15495.36,6141 v3(15522.36,6168)
  Bottom Layer w20: U21.1@14801.44,6170.94 14764.91,6170.94 14724.56,6211.28 14724.56,6262.29 14762.93,6300.65 U121.2@14803.12,6300.65 ; U21.1@14802.7,6176 14848.36,6130.34 v3(14848.36,5874) ; U121.2@14803.12,6295.4 U121.2@14803.12,6300.65 ; L2.2@14824.36,6541.44 14824.55,6541.25 C182.1@14921.43,6541.25 ; C141.2@15074.57,6244.61 15074.77,6244.81 15074.77,6247 v3(15074.77,6282.77) ; C143.2@15075.9,6464 15075.9,6528.46 15063.82,6540.54 C129.1@15015.36,6540.54 14923.07,6540.54 C182.1@14922.36,6541.25 C182.1@14921.43,6541.25 ; U121.2@14803.12,6300.65 14803.12,6373.16 14850.18,6420.22 14850.18,6445.49 14921.43,6516.74 C182.1@14921.43,6541.25
410_HSYNC: RN1.6 U3.4 | length 921.2
  Top Layer w4.7: RN1.6@14792.2,6964.17 14792.2,6925.84 14787.36,6921 14787.36,6910.56 ccw(c14794.36,6910.56) 14794.36,6903.56 cw(c14794.36,6896.56) 14801.36,6896.56 14801.36,6895.56 cw(c14794.36,6895.56) 14794.36,6888.56 14780.36,6888.56 ccw(c14780.36,6881.56) 14773.36,6881.56 14773.36,6880.56 ccw(c14780.36,6880.56) 14780.36,6873.56 14794.36,6873.56 cw(c14794.36,6866.56) 14801.36,6866.56 14801.36,6865.56 cw(c14794.36,6865.56) 14794.36,6858.56 14780.36,6858.56 ccw(c14780.36,6851.56) 14773.36,6851.56 14773.36,6850.56 ccw(c14780.36,6850.56) 14780.36,6843.56 14794.36,6843.56 cw(c14794.36,6836.56) 14801.36,6836.56 14801.36,6835.56 cw(c14794.36,6835.56) 14794.36,6828.56 14780.36,6828.56 ccw(c14780.36,6821.56) 14773.36,6821.56 14773.36,6820.56 ccw(c14780.36,6820.56) 14780.36,6813.56 14794.36,6813.56 cw(c14794.36,6806.56) 14801.36,6806.56 14801.36,6805.56 cw(c14794.36,6805.56) 14794.36,6798.56 14780.36,6798.56 ccw(c14780.36,6791.56) 14773.36,6791.56 14773.36,6790.56 ccw(c14780.36,6790.56) 14780.36,6783.56 14794.36,6783.56 cw(c14794.36,6776.56) 14801.36,6776.56 14801.36,6775.56 cw(c14794.36,6775.56) 14794.36,6768.56 14780.36,6768.56 ccw(c14780.36,6761.56) 14773.36,6761.56 14773.36,6760.56 ccw(c14780.36,6760.56) 14780.36,6753.56 cw(c14780.36,6746.56) 14787.36,6746.56 14787.36,6541 14923.78,6404.58 U3.4@15012.95,6404.58
410_HSYNC_FPGA: RN1.3 U8.Y10 | length 700.8
  Top Layer w4.7: v3(14791.36,7020) 14791.36,6998.67 RN1.3@14792.2,6997.83
  Top Layer w10: v2(14528.63,7561.68) U8.Y10@14548.3,7581.35
  L6_SIG2 w5: v2(14528.63,7561.68) 14555.14,7535.17 14555.14,7275.22 14791.36,7039 v3(14791.36,7020)
410_PVDD: C128.2 C135.1 C136.1 C145.2 C146.2 C184.1 L4.2 U3.18 | length 538.2
  Top Layer w10: U3.18@15109.41,6091.59 15109.41,6153.05 15118.36,6162 v3(15153.36,6162)
  Bottom Layer w10: v3(15153.36,6162) 15149.36,6166 C146.2@15118.82,6166 C145.2@15118.82,6126 C136.1@15118.82,6086 C135.1@15118.82,6046 15118.82,5978.09 C128.2@15116.73,5976 15132.11,5960.62 C184.1@15132.11,5866 L4.2@15217.8,5866
410_PWR: C212.2 L2.1 L3.1 L4.1 L30.2 | length 122.8
  Top Layer w50: L30.2@15940.93,5955.66 15940.93,5833.47 C212.2@15941.39,5833
  other v1: 16008.36,5798 16042.36,5798 16042.36,5832 16007.36,5833 16008.36,5866 16043.36,5866
410_TVDD: C132.1 C133.1 C142.2 C144.2 C183.1 L3.2 R98.2 U3.23 U3.29 | length 562.1
  Top Layer w10: R98.2@15121.4,6016 15144.36,6016 v3(15153.36,6025) ; U3.23@15207.83,6091.59 v3(15207.83,6130) ; U3.29@15325.94,6091.59 15326.36,6092.01 v3(15326.36,6131)
  Bottom Layer w10: v3(15153.36,6025) 15207.83,6079.47 v3(15207.83,6130) C144.2@15207.83,6154.07 ; C144.2@15207.36,6154.54 C144.2@15207.83,6154.07 ; C132.1@15247.36,6154.54 C132.1@15246.89,6154.07 ; v3(15326.36,6131) 15326.36,6153.54 C142.2@15326.89,6154.07 ; C133.1@15367.36,6154.54 C142.2@15327.36,6154.54 C142.2@15326.89,6154.07 ; C144.2@15207.83,6154.07 C132.1@15246.89,6154.07 ; C132.1@15246.89,6154.07 C142.2@15326.89,6154.07
  Bottom Layer w20: C183.1@15457.61,6046 15457.61,5993.19 L3.2@15499.8,5951
410_VSYNC: RN1.7 U3.5 | length 1049.9
  Top Layer w4.7: RN1.7@14772.52,6964.17 14772.52,6928.16 14760.36,6916 14760.36,6727.42 ccw(c14767.86,6727.42) 14767.86,6719.92 cw(c14767.86,6712.42) 14767.86,6704.92 14752.86,6704.92 ccw(c14752.86,6697.42) 14752.86,6689.92 14767.86,6689.92 cw(c14767.86,6682.42) 14767.86,6674.92 14752.86,6674.92 ccw(c14752.86,6667.42) 14752.86,6659.92 14767.86,6659.92 cw(c14767.86,6652.42) 14767.86,6644.92 14752.86,6644.92 ccw(c14752.86,6637.42) 14752.86,6629.92 14767.86,6629.92 cw(c14767.86,6622.42) 14767.86,6614.92 14752.86,6614.92 ccw(c14752.86,6607.42) 14752.86,6599.92 14767.86,6599.92 cw(c14767.86,6592.42) 14767.86,6584.92 14752.86,6584.92 ccw(c14752.86,6577.42) 14752.86,6569.92 cw(c14752.86,6562.42) 14760.36,6562.42 14760.36,6532 14781.7,6510.66 ccw(c14785.93,6514.88) 14790.15,6510.66 cw(c14794.38,6506.43) 14798.61,6510.66 14800.76,6508.5 cw(c14796.53,6504.27) 14800.76,6500.05 14792.31,6491.6 ccw(c14796.53,6487.37) 14792.31,6483.14 14794.46,6480.99 ccw(c14798.69,6485.22) 14802.92,6480.99 14811.37,6489.44 cw(c14815.59,6485.22) 14819.82,6489.44 14821.97,6487.29 cw(c14817.75,6483.06) 14821.97,6478.84 14813.52,6470.38 ccw(c14817.75,6466.16) 14813.52,6461.93 14815.68,6459.78 ccw(c14819.9,6464) 14824.13,6459.78 cw(c14828.35,6455.55) 14832.58,6459.78 14907.46,6384.9 U3.5@15012.95,6384.9
410_VSYNC_FPGA: RN1.2 U8.AA10 | length 659.9
  Top Layer w4.7: v3(14772.36,7036) 14772.36,6997.99 RN1.2@14772.52,6997.83
  Top Layer w10: v2(14528.63,7522.32) U8.AA10@14548.3,7542
  L6_SIG2 w5: v2(14528.63,7522.32) 14541.48,7509.47 14541.48,7255.71 14761.19,7036 v3(14772.36,7036)
7125_3V3: C106.1 C107.2 C108.1 C109.2 C110.2 L33.2 Q1.1 Q2.1 Q3.1 Q4.1 R81.1 R82.1 R83.2 R87.2 R88.2 R89.2 R92.2 R93.2 U4.13 U4.29 U4.30 | length 974.4
  Top Layer w4.7: R89.2@13464.09,5991.04 13464.09,5954.39 Q2.1@13483.76,5934.72 ; R88.2@13609.09,5996.04 13609.09,5955.77 Q1.1@13629.45,5935.41 ; R92.2@13754.09,5996.04 13754.09,5955.77 Q3.1@13774.45,5935.41 ; R93.2@13899.09,5996.04 13899.09,5955.77 Q4.1@13919.45,5935.41
  Top Layer w10: U4.13@13917.5,6438.27 v3(13942.36,6438.27) ; U4.29@14021.83,6196.14 14021.83,6176.53 14025.36,6173 14038.36,6173 14041.52,6176.16 U4.30@14041.52,6196.14 v3(14041.52,6220)
  Top Layer w20: R89.2@13464.09,5991.04 13464.09,6048.08 v3(13464.21,6048.2) ; R88.2@13609.09,5996.04 13609.09,6048.49 v3(13609.26,6048.67) ; v3(13753.84,6048.9) 13754.09,6048.66 R92.2@13754.09,5996.04 ; v3(13898.95,6058.39) 13899.09,6058.26 R93.2@13899.09,5996.04 ; R87.2@14323.4,6290 v3(14349.32,6290)
  Bottom Layer w15: v3(13884.36,6481) 13874.36,6491 13874.36,6534 13890.4,6550.04 R82.1@13908.36,6550.04 ; v3(14041.52,6220) 14051.36,6229.84 C108.1@14051.36,6243.54
  Bottom Layer w20: v3(13637.49,6109.49) 13637.49,6161.16 L33.2@13638.2,6161.86 ; C106.1@13895.82,6402 C107.2@13895.82,6438 13942.09,6438 v3(13942.36,6438.27) ; R82.1@13908.36,6550.04 R81.1@13948.36,6550.04 ; C109.2@14011.36,6243.54 C108.1@14051.36,6243.54
7125_B0: RN17.5 U4.16 | length 1126.7
  Top Layer w4.7: U4.16@13917.5,6379.21 13788.15,6379.21 13779.36,6388 13779.36,6548.72 cw(c13789.36,6548.72) 13789.36,6558.72 13830.01,6558.72 ccw(c13830.01,6568.72) 13830.01,6578.72 13789.36,6578.72 cw(c13789.36,6588.72) 13789.36,6598.72 13830.01,6598.72 ccw(c13830.01,6608.72) 13830.01,6618.72 13789.36,6618.72 cw(c13789.36,6628.72) 13789.36,6638.72 13830.01,6638.72 ccw(c13830.01,6648.72) 13830.01,6658.72 13789.36,6658.72 cw(c13789.36,6668.72) 13779.36,6668.72 13779.36,6685.41 14011.36,6917.41 14011.36,6963.64 RN17.5@14011.89,6964.17
7125_B0_FPGA: RN17.4 U8.AB4 | length 629.1
  Top Layer w4.7: RN17.4@14011.89,6997.83 14011.89,7052.53 v3(14012.36,7053)
  Top Layer w10: v2(14292.41,7482.92) U8.AB4@14312.08,7502.6
  L6_SIG2 w5: v3(14012.36,7053) 14012.36,7065 14292.41,7345.05 v2(14292.41,7482.92)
